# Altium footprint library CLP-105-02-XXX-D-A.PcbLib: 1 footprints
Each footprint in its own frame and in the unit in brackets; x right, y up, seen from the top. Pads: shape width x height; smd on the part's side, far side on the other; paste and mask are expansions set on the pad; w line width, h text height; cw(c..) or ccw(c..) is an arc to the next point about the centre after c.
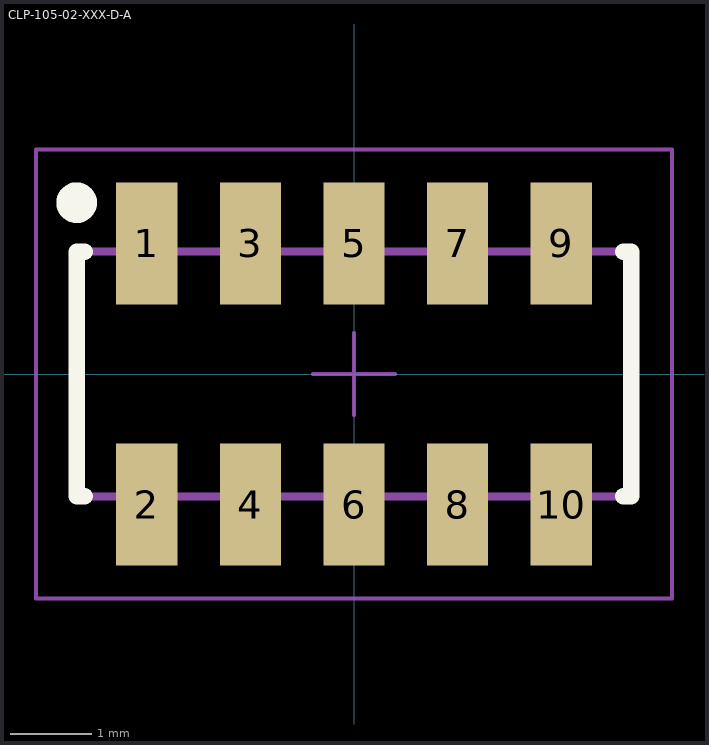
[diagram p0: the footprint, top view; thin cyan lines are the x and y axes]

## CLP-105-02-XXX-D-A [mm] "1.27mm pitch, 10 pin, socket; low profile, double row, SMT"
height 2.26
pads (10):
  rect 0.75x1.5 smd mask+0: 1(-2.54,1.6) 2(-2.54,-1.6) 3(-1.27,1.6) 4(-1.27,-1.6) 5(0,1.6) 6(0,-1.6) 7(1.27,1.6) 8(1.27,-1.6) 9(2.54,1.6) 10(2.54,-1.6)
Top Overlay:
  circle w0.25: c-3.4,2.1 r0.125
  lines w0.2: -3.3,-1.5 -3.4,-1.5 -3.4,1.5 -3.3,1.5 ; 3.3,-1.5 3.4,-1.5 3.4,1.5 3.3,1.5
Mechanical 12:
  lines w0.001: -3.4,-1.5 3.4,-1.5 3.4,1.5 -3.4,1.5 -3.4,-1.5
Mechanical 13:
  lines w0.1: -3.4,-1.5 3.4,-1.5 3.4,1.5 -3.4,1.5 -3.4,-1.5
  text ".Designator" at 0.254,0.254 h1.52
Mechanical 15:
  lines w0.05: -0.5,0 0.5,0 ; 0,-0.5 0,0.5 ; -3.9,-2.75 3.9,-2.75 3.9,2.75 -3.9,2.75 -3.9,-2.75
